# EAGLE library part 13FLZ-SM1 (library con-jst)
CONNECTOR
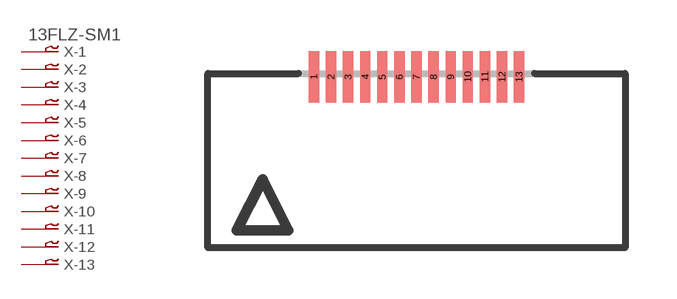
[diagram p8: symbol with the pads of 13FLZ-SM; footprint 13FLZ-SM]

Designator prefix X; gates -1=P-VN -2=P-N -3=P-N -4=P-N -5=P-N -6=P-N -7=P-N -8=P-N -9=P-N -10=P-N -11=P-N -12=P-N -13=P-N

## 13FLZ-SM1 (OC_FARNELL: unknown; OC_NEWARK: unknown)  [13FLZ-SM]
1  -1:1  pas
2  -2:1  pas
3  -3:1  pas
4  -4:1  pas
5  -5:1  pas
6  -6:1  pas
7  -7:1  pas
8  -8:1  pas
9  -9:1  pas
10  -10:1  pas
11  -11:1  pas
12  -12:1  pas
13  -13:1  pas

## Footprint 13FLZ-SM (pad centres in mm)
CONNECTOR
smd 0.3 x 1.5: 1 -3,2.5; 2 -2.5,2.5; 3 -2,2.5; 4 -1.5,2.5; 5 -1,2.5; 6 -0.5,2.5; 7 0,2.5; 8 0.5,2.5; 9 1,2.5; 10 1.5,2.5; 11 2,2.5; 12 2.5,2.5; 13 3,2.5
